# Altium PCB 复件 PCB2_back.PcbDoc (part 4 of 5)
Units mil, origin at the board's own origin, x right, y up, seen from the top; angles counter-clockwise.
Board outline 6299 x 3937 mil, 4 copper layers (TopLayer, GROUND, VCC, BottomLayer); 290 components, 470 nets, 2252 pads, 827 vias.
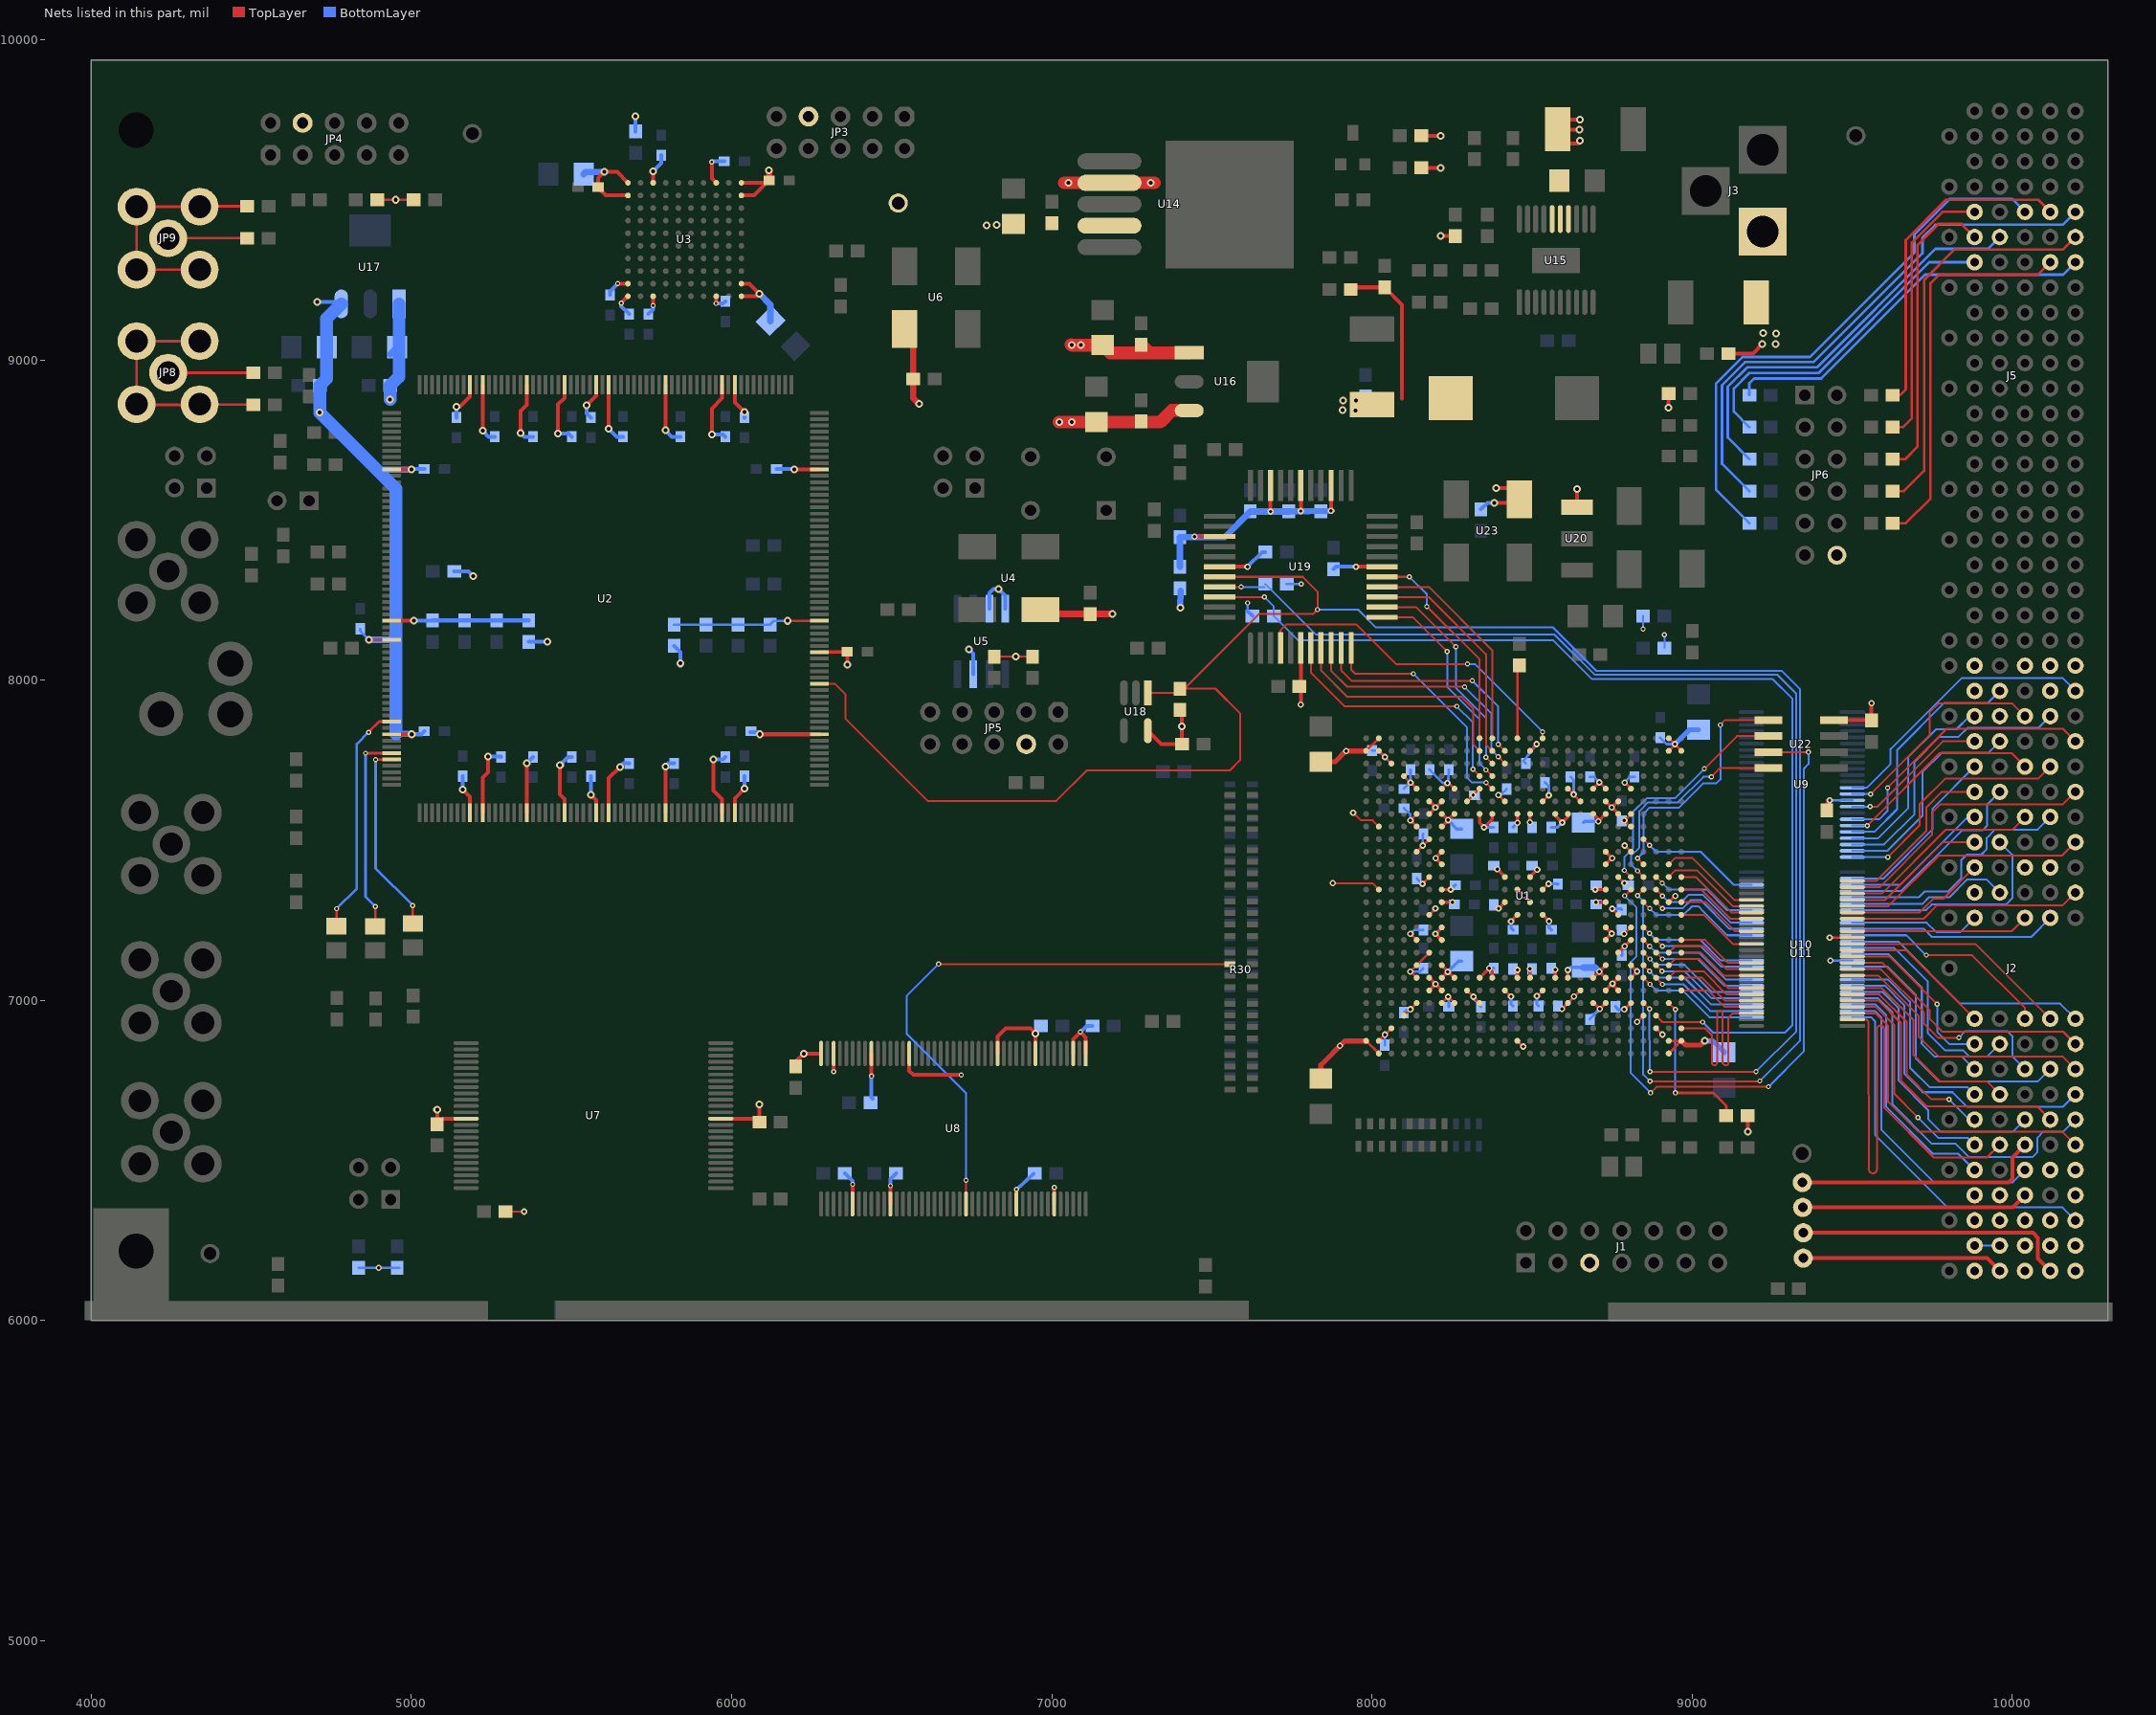
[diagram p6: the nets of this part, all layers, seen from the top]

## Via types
v1: diameter 16, hole 8, TopLayer to BottomLayer, 408 vias
v2: diameter 20, hole 10, TopLayer to BottomLayer, 220 vias
v3: diameter 24, hole 12, TopLayer to BottomLayer, 196 vias
v4: diameter 56.69, hole 56.69, TopLayer to BottomLayer, 2 vias
v5: diameter 20, hole 0, TopLayer to BottomLayer, 1 vias

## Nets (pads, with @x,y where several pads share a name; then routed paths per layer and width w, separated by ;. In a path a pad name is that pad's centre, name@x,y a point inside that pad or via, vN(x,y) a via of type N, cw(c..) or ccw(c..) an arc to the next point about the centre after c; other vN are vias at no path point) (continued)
P_AD22: U1.L4 U10.34 | length 379.9
  TopLayer w6: U1.L4@8847.89,7227.7 v1(8866.59,7209)
  BottomLayer w6: v1(8866.59,7209) 8886.59,7189 9025,7189 9089.59,7124.41 U10.34@9185.04,7124.41
P_AD23: U1.K1 U11.38 | length 248.6
  TopLayer w6: U1.K1@8966,7188.33 9040.67,7188.33 9112.15,7116.85 U11.38@9185.04,7116.85
P_AD24: U1.K4 U10.31 | length 388.1
  TopLayer w6: U1.K4@8847.89,7188.33 v1(8867.22,7169)
  BottomLayer w6: v1(8867.22,7169) 8887.22,7149 9021,7149 9104.65,7065.35 U10.31@9185.04,7065.35
P_AD25: U1.J1 U11.40 | length 248.6
  TopLayer w6: U1.J1@8966,7148.96 9026.04,7148.96 9097.52,7077.48 U11.40@9185.04,7077.48
P_AD26: U1.J3 U10.30 | length 340.6
  TopLayer w6: U1.J3@8887.26,7148.96 v1(8907.22,7129)
  BottomLayer w6: v1(8907.22,7129) 9017,7129 9100.33,7045.67 U10.30@9185.04,7045.67
P_AD27: U1.H2 U11.42 | length 304.1
  TopLayer w6: U1.H2@8926.63,7109.59 8946.04,7129 9023,7129 9113.89,7038.11 U11.42@9185.04,7038.11
P_AD28: U1.J4 U10.29 | length 388.1
  TopLayer w6: U1.J4@8847.89,7148.96 v1(8867.85,7129)
  BottomLayer w6: v1(8867.85,7129) 8885.85,7111 8976,7111 9061.01,7025.98 U10.29@9185.04,7025.98
P_AD29: U1.G2 U11.43 | length 297.1
  TopLayer w6: U1.G2@8926.63,7070.22 8947.41,7091 9035,7091 9107.58,7018.43 U11.43@9185.04,7018.43
P_AD30: U1.H3 U10.28 | length 340.6
  TopLayer w6: U1.H3@8887.26,7109.59 v1(8905.85,7091)
  BottomLayer w6: v1(8905.85,7091) 8976,7091 9060.7,7006.3 U10.28@9185.04,7006.3
P_AD31: U1.G1 U11.44 | length 248.6
  TopLayer w6: U1.G1@8966,7070.22 9030.78,7070.22 9102.26,6998.74 U11.44@9185.04,6998.74
P_CBE0: U1.V4 U10.46 | length 396.2
  TopLayer w6: U1.V4@8847.89,7503.29 v1(8867.18,7484)
  BottomLayer w6: v1(8867.18,7484) 8887.18,7464 9027,7464 9130.37,7360.63 U10.46@9185.04,7360.63
P_CBE1: U1.T2 U11.28 | length 320.4
  TopLayer w6: U1.T2@8926.63,7424.55 8946.08,7444 9001,7444 9131.3,7313.7 U11.28@9185.04,7313.7
P_CBE2: U1.M1 U11.35 | length 256.8
  TopLayer w6: U1.M1@8966,7267.07 9035.93,7267.07 9127.09,7175.9 U11.35@9185.04,7175.9
P_CBE3: U1.J2 U11.39 | length 296.5
  TopLayer w6: U1.J2@8926.63,7148.96 8946.67,7169 9035,7169 9106.83,7097.16 U11.39@9185.04,7097.16
P_CLK: U1.C1 U11.46 | length 796.4
  TopLayer w6: U1.C1@8966,6912.74 9039.26,6912.74 9062,6890 9062,6802 9066,6798 9073,6798 9078,6803 9078,6961 9084,6967 9090,6967 9095,6962 9095,6803 9101,6797 9109,6797 9113,6801 9113,6946 9126.37,6959.37 U11.46@9185.04,6959.37
P_DEVSEL: U1.P1 U11.31 | length 256.8
  TopLayer w6: U1.P1@8966,7345.81 9028.19,7345.81 9119.35,7254.65 U11.31@9185.04,7254.65
P_EN: R61.1 U1.E2 | length 495.7
  TopLayer w6: U1.E2@8926.63,6991.48 v1(8947,6971.11)
  TopLayer w8: v1(8947,6711) 9066,6711 9106.54,6670.46 R61.1@9106.54,6640
  BottomLayer w6: v1(8947,6711) v1(8947,6971.11)
P_FRAME: U1.N4 U10.38 | length 401.8
  TopLayer w6: U1.N4@8847.89,7306.44 v1(8867.33,7287)
  BottomLayer w6: v1(8867.33,7287) 8887.33,7267 8973,7267 8999,7293 9020,7293 9036,7277 ; 9035.5,7276.5 9108.85,7203.15 U10.38@9185.04,7203.15
P_GNT: U1.H4 U10.27 | length 388.1
  TopLayer w6: U1.H4@8847.89,7109.59 v1(8866.48,7091)
  BottomLayer w6: v1(8866.48,7091) 8886.48,7071 8975,7071 9059.39,6986.61 U10.27@9185.04,6986.61
P_IDSEL: U1.K3 U10.33 | length 332.4
  TopLayer w6: U1.K3@8887.26,7188.33 v1(8906.59,7169)
  BottomLayer w6: v1(8906.59,7169) 9026,7169 9090.27,7104.73 U10.33@9185.04,7104.73
P_INTA: U1.G4 U10.25 | length 388.1
  TopLayer w6: U1.G4@8847.89,7070.22 v1(8868.11,7050)
  BottomLayer w6: v1(8868.11,7050) 8887.11,7031 8970,7031 9053.75,6947.24 U10.25@9185.04,6947.24
P_IRDY: U1.N1 U11.33 | length 256.8
  TopLayer w6: U1.N1@8966,7306.44 9042.56,7306.44 9133.73,7215.27 U11.33@9185.04,7215.27
P_PAR: U1.P3 U10.40 | length 358.8
  TopLayer w6: U1.P3@8887.26,7345.81 v1(8907.07,7326)
  BottomLayer w6: v1(8907.07,7326) 8926.07,7307 8966,7307 8988,7329 9034,7329 9120.48,7242.52 U10.40@9185.04,7242.52
P_PERR: U1.R1 U11.30 | length 265
  TopLayer w6: U1.R1@8966,7385.18 9010.82,7385.18 9121.67,7274.33 U11.30@9185.04,7274.33
P_REQ: U1.F1 U11.45 | length 240.5
  TopLayer w6: U1.F1@8966,7030.85 9049.15,7030.85 9100.94,6979.06 U11.45@9185.04,6979.06
P_RST: U1.G3 U10.26 | length 340.6
  TopLayer w6: U1.G3@8887.26,7070.22 v1(8907.48,7050)
  BottomLayer w6: v1(8907.48,7050) 8973,7050 9056.07,6966.93 U10.26@9185.04,6966.93
P_SERR: U1.R2 U11.29 | length 312.6
  TopLayer w6: U1.R2@8926.63,7385.18 8946.45,7405 9016,7405 9126.99,7294.02 U11.29@9185.04,7294.02
P_STOP: U1.R3 U10.42 | length 340.6
  TopLayer w6: U1.R3@8887.26,7385.18 v1(8906.44,7366)
  BottomLayer w6: v1(8906.44,7366) 8926.44,7346 9044,7346 9108.11,7281.89 U10.42@9185.04,7281.89
P_TRDY: U1.N3 U10.39 | length 353.9
  TopLayer w6: U1.N3@8887.26,7306.44 v1(8906.7,7287)
  BottomLayer w6: v1(8906.7,7287) 8970,7287 8996,7313 9026,7313 9116.17,7222.84 U10.39@9185.04,7222.84
PCI_EEAI: R78.1 U1.L5 | length 29.2
  TopLayer w8: v2(8787,7208) U1.L5@8808.52,7227.7
PXI_3.3V: J2.C6 pad.1@9344,6431 | length 783.2
  TopLayer w12: pad.1@9344,6431 9988,6431 10000,6443 10000,6509.51 J2.C6@10039.37,6548.88
PXI_+12V: J2.D1 pad.4 | length 630.1
  TopLayer w12: pad.4@9347,6195 9920.81,6195 J2.D1@9960.63,6155.18
PXI_-12V: J2.B1 pad.3 | length 858.2
  TopLayer w12: pad.3@9347,6274 10064,6274 10080,6258 10080,6193.29 J2.B1@10118.11,6155.18
PXI_ACK64#: J2.E24
PXI_AD0: J2.D24 U9.20 | length 758.2
  BottomLayer w6: U9.20@9500,7525.98 9569,7525.98 9640,7596.98 9640,7782 9786,7928 9922.49,7928 J2.D24@9965.49,7971
PXI_AD1: J2.A24 U9.13 | length 882.9
  BottomLayer w6: U9.13@9500,7663.78 9544.78,7663.78 9619.67,7738.67 9619.67,7784.67 9842,8007 10155.99,8007 J2.A24@10196.85,7966.14
PXI_AD2: J2.E23 U9.21 | length 633.3
  BottomLayer w6: U9.21@9500,7506.3 9581,7506.3 9674,7599.3 9674,7759 9761.41,7846.41 9825.41,7846.41 9866.4,7887.4 J2.E23@9881.89,7887.4
PXI_AD3: J2.C23 U9.14 | length 714.5
  TopLayer w6: v1(9557.09,7644.1) 9741,7828 9741,7899 9769,7927 9999.77,7927 J2.C23@10039.37,7887.4
  BottomLayer w6: U9.14@9500,7644.1 v1(9557.09,7644.1)
PXI_AD4: J2.B23 U9.22 | length 879.2
  BottomLayer w6: U9.22@9500,7486.61 9599,7486.61 9694,7581.61 9694,7744 9772.9,7822.9 9831.9,7822.9 9860,7851 10081.71,7851 J2.B23@10118.11,7887.4
PXI_AD5: J2.E22 U9.16 | length 466.4
  TopLayer w6: v1(9555.73,7604.73) 9578.73,7604.73 9782.66,7808.66 J2.E22@9881.89,7808.72
  BottomLayer w6: U9.16@9500,7604.73 v1(9555.73,7604.73)
PXI_AD6: J2.D22 U9.23 | length 682.5
  BottomLayer w6: U9.23@9500,7466.93 9610,7466.93 9719,7575.93 9719,7713 9779,7773 9924.97,7773 J2.D22@9960.63,7808.72
PXI_AD7: J2.A22 U9.18 | length 872.4
  TopLayer w6: v1(9610,7663) 9795,7848 10157.51,7848 J2.A22@10196.85,7808.72
  BottomLayer w6: U9.18@9500,7565.35 9584.35,7565.35 9610,7591 v1(9610,7663)
PXI_AD8: J2.C21 U9.19 | length 650.5
  TopLayer w6: v1(9546.67,7545.67) 9773,7772 9997.29,7772 J2.C21@10039.37,7729.92
  BottomLayer w6: U9.19@9500,7545.67 v1(9546.67,7545.67)
PXI_AD9: J2.B21 U9.24 | length 773.9
  TopLayer w6: v1(9611.25,7447.24) 9710.28,7546.28 9710.28,7612.28 9790,7692 10080.19,7692 J2.B21@10118.11,7729.92
  BottomLayer w6: U9.24@9500,7447.24 v1(9611.25,7447.24)
PXI_AD10: J2.E20 U11.24 | length 540
  TopLayer w6: U11.24@9500,7372.76 9574.75,7372.76 9731.25,7529.25 9731.25,7602.25 9780.18,7651.18 J2.E20@9881.89,7651.24
PXI_AD11: J2.D20 U10.4 | length 628.1
  BottomLayer w6: U10.4@9500,7340.94 9651.94,7340.94 9842,7531 9907,7531 9921,7545 9921,7611.55 J2.D20@9960.63,7651.24
PXI_AD12: J2.A20 U11.23 | length 860.8
  TopLayer w6: U11.23@9500,7353.07 9585.07,7353.07 9748.62,7516.62 9748.62,7585.62 9775,7612 10157.67,7612 J2.A20@10196.85,7651.24
PXI_AD13: J2.E19 U10.3 | length 469.6
  BottomLayer w6: U10.3@9500,7360.63 9648.63,7360.63 9860.44,7572.44 J2.E19@9881.89,7572.44
PXI_AD14: J2.C19 U11.22 | length 638.4
  TopLayer w6: U11.22@9500,7333.39 9592.39,7333.39 9791,7532 9998.93,7532 J2.C19@10039.37,7572.44
PXI_AD15: J2.B19 U10.5 | length 775.5
  BottomLayer w6: U10.5@9500,7321.26 9707.37,7321.26 9726,7339.89 9798.89,7339.89 9840,7381 9840,7437 9858,7455 9903,7455 9920,7472 9920,7507 9946,7533 10078.67,7533 J2.B19@10118.11,7572.44
PXI_AD16: J2.C11 U10.11 | length 666.7
  TopLayer w6: v1(9731,7141) 9874,7141 10039.37,6975.63 J2.C11@10039.37,6942.52
  BottomLayer w6: U10.11@9500,7203.15 9668.85,7203.15 v1(9731,7141)
PXI_AD17: J2.B11 U11.14 | length 714.8
  TopLayer w6: U11.14@9500,7175.9 9884.72,7175.9 J2.B11@10118.11,6942.52
PXI_AD18: J2.A11 U10.12 | length 796.7
  BottomLayer w6: U10.12@9500,7183.47 9643.53,7183.47 9837,6990 10149.37,6990 J2.A11@10196.85,6942.52
PXI_AD19: J2.E10 U11.12 | length 545.8
  TopLayer w6: U11.12@9500,7136.53 9616.47,7136.53 v1(9765,6988)
  BottomLayer w6: v1(9765,6988) 9765,6901 9802.22,6863.78 J2.E10@9881.89,6863.84
PXI_AD20: J2.D10 U10.13 | length 711.9
  BottomLayer w6: U10.13@9500,7163.78 9630.22,7163.78 9736,7058 9736,6897.39 9789,6844.39 9845.61,6844.39 9866,6824 9920.85,6824 J2.D10@9960.63,6863.84
PXI_AD21: J2.A10 U11.11 | length 818.1
  TopLayer w6: U11.11@9500,7116.85 9594.15,7116.85 9742,6969 9742,6941 9781,6902 10158.63,6902 J2.A10@10196.85,6863.84
PXI_AD22: J2.E9 U10.14 | length 633.7
  BottomLayer w6: U10.14@9500,7144.1 9612.91,7144.1 9717,7040 9717,6864 9757,6824 9842.93,6824 J2.E9@9881.89,6785.04
PXI_AD23: J2.C9 U11.10 | length 743.3
  TopLayer w6: U11.10@9500,7097.16 9588.83,7097.16 9724,6962 9724,6927 9768,6883 v1(9833,6883)
  BottomLayer w6: v1(9833,6883) 9852,6903 9985,6903 10000,6888 10000,6824.47 J2.C9@10039.37,6785.1
PXI_AD24: J2.E8 U10.18 | length 651.3
  BottomLayer w6: U10.18@9500,7065.35 9610.65,7065.35 9680,6996 9680,6790 9742,6728 9860.19,6728 J2.E8@9881.89,6706.3
PXI_AD25: J2.D8 U11.7 | length 661.9
  TopLayer w6: U11.7@9500,7038.11 9590.89,7038.11 9691.07,6937.93 9691.07,6828.93 9773,6747 9919.93,6747 J2.D8@9960.63,6706.3
PXI_AD26: J2.A8 U10.19 | length 994.5
  BottomLayer w6: U10.19@9500,7045.67 9601.33,7045.67 9663,6984 9663,6770 9720,6713 9813,6713 9858,6668 10158.55,6668 J2.A8@10196.85,6706.3
PXI_AD27: J2.E7 U11.6 | length 642.4
  TopLayer w6: U11.6@9500,7018.43 9584.58,7018.43 9670,6933 9670,6768 9747,6691 v1(9802,6691)
  BottomLayer w6: v1@9802,6689 v1@9804,6689 ; v1(9802,6691) 9865.44,6627.56 J2.E7@9881.89,6627.62
PXI_AD28: J2.C7 U10.20 | length 885.1
  BottomLayer w6: U10.20@9500,7025.98 9594.01,7025.98 9645,6975 9645,6749 9737,6657 9737,6629 9777,6589 10000.81,6589 J2.C7@10039.37,6627.62
PXI_AD29: J2.B7 U11.5 | length 877.3
  TopLayer w6: U11.5@9500,6998.74 9582.26,6998.74 9652,6929 9652,6749 9732,6669 10076.67,6669 J2.B7@10118.11,6627.62
PXI_AD30: J2.A7 U10.21 | length 1145.6
  BottomLayer w6: U10.21@9500,7006.3 9580.7,7006.3 9625,6962 9625,6675 9747,6553 9822,6553 9865,6510 10062,6510 10078,6526 10078,6571 10097,6590 10159.29,6590 J2.A7@10196.85,6627.62
PXI_AD31: J2.E6 U11.4 | length 685.5
  TopLayer w6: U11.4@9500,6979.06 9573.94,6979.06 9631,6922 9631,6708 v1(9705,6634)
  BottomLayer w6: v1(9705,6634) 9768,6571 9859.71,6571 J2.E6@9881.89,6548.82
PXI_BRSVP1A5: J2.A5
PXI_BRSVP1B5: J2.B5
PXI_C/BE0#: J2.E21 U10.2 | length 569
  BottomLayer w6: U10.2@9500,7380.31 9597,7380.31 9751,7534.31 9751,7599.03 J2.E21@9884.97,7733
PXI_C/BE1#: J2.E18 U11.21 | length 467.3
  TopLayer w6: U11.21@9500,7313.7 9602.7,7313.7 9782.7,7493.7 J2.E18@9892.7,7493.7
PXI_C/BE2#: J2.E11 U11.13 | length 470.4
  TopLayer w6: U11.13@9500,7156.22 9668.19,7156.22 J2.E11@9881.89,6942.52
PXI_C/BE3#: J2.A9 U11.9 | length 856.1
  TopLayer w6: U11.9@9500,7077.48 9581.52,7077.48 9708,6951 9708,6886 9769,6825 10156.89,6825 J2.A9@10196.85,6785.04
PXI_CLK10: J5.E17 R89.1 | length 947.1
  TopLayer w8: R89.1@9625.46,8690 9665,8690 9704,8729 9704,9359 9770,9425 9840.42,9425 J5.E17@9881.89,9383.53
PXI_DEVSEL#: J2.A16 U11.18 | length 730.6
  TopLayer w6: U11.18@9500,7254.65 9722.65,7254.65 9765,7297 10157.63,7297 J2.A16@10196.85,7336.22
PXI_ENUM#: J2.C25
PXI_FRAME#: J2.B15 U10.10 | length 658
  BottomLayer w6: U10.10@9500,7222.84 9724.17,7222.84 9749,7198 10058.63,7198 J2.B15@10121.63,7261
PXI_GNT#: J2.E5 U10.22 | length 764
  BottomLayer w6: U10.22@9500,6986.61 9573.39,6986.61 9606,6954 9606,6667 9752,6521 9830.97,6521 J2.E5@9881.89,6470.14
PXI_IDSEL: J2.B9 U10.16 | length 898.9
  BottomLayer w6: U10.16@9500,7104.73 9610.27,7104.73 9699,7016 9699,6818 9771,6746 10079.07,6746 J2.B9@10118.11,6785.04
PXI_INTA#: J2.A3 U10.24 | length 1173.8
  BottomLayer w6: U10.24@9500,6947.24 9558.75,6947.24 9571,6935 9571,6580 9798,6353 10156.51,6353 J2.A3@10196.85,6312.66 ; J2.A3@10196.88,6312.63 J2.A3@10201.25,6317
PXI_INTB#: J2.B3
PXI_INTC#: J2.C3
PXI_INTD#: J2.E3
PXI_INTP: J2.D4
PXI_INTS: J2.E4
PXI_IPMB_PWR: J2.A4
PXI_IPMB_SCL: J2.B17
PXI_IPMB_SDA: J2.C17
PXI_IRDY#: J2.C15 U11.16 | length 556.9
  TopLayer w6: U11.16@9500,7215.27 9997.16,7215.27 J2.C15@10039.37,7257.54
PXI_LOCK#: J2.E16
PXI_PAR: J2.D18 U10.7 | length 706.4
  BottomLayer w6: U10.7@9500,7281.89 9730.89,7281.89 9748,7299 9980,7299 10000,7319 10000,7454.33 J2.D18@9960.63,7493.7
PXI_PCLK: J2.D6 U11.2 | length 1714.1
  TopLayer w6: U11.2@9500,6939.69 9544.32,6939.69 9551,6933 9551.15,6474.98 ccw(c9564,6473) 9577,6473 9577,6911 cw(c9588,6910) 9599.05,6910 ; 9599,6910 9599,6665 9755,6509 9920.81,6509 J2.D6@9960.63,6548.82
PXI_PERR#: J2.E17 U11.19 | length 440.1
  TopLayer w6: U11.19@9500,7274.33 9710.33,7274.33 9754,7318 9784.93,7318 J2.E17@9881.89,7415.02
PXI_REQ64#: J2.B25
PXI_REQ#: J2.A6 U11.3 | length 1005.7
  TopLayer w6: U11.3@9500,6959.37 9572.63,6959.37 9612,6920 9612,6683 9706,6589 10156.67,6589 J2.A6@10196.85,6548.82
PXI_RST#: J2.C5 U10.23 | length 982.3
  BottomLayer w6: U10.23@9500,6966.93 9570.07,6966.93 9590,6947 9590,6596 9754,6432 10001.29,6432 J2.C5@10039.37,6470.14
PXI_SERR#: J2.A18 U11.20 | length 779.6
  TopLayer w6: U11.20@9500,7294.02 9613.01,7294.02 9771,7452 10155.15,7452 J2.A18@10196.85,7493.7
PXI_START: J5.D17 R53.2 | length 1297.3
  BottomLayer w8: R53.2@9178.54,8690 9111,8757.54 9111,8916 9172,8977 9390,8977 9760,9347 9924.1,9347 J5.D17@9960.63,9383.53
PXI_STOP#: J2.D16 U10.6 | length 508.8
  BottomLayer w6: U10.6@9500,7301.57 9719.58,7301.57 9740.03,7322.03 9803.03,7322.03 9858,7377 9919.85,7377 J2.D16@9960.63,7336.22
PXI_TCK: J2.A2
PXI_TDIO: J2.D2 J2.E2 | length 78.7
  BottomLayer w6: J2.E2@9881.89,6233.92 J2.D2@9960.63,6233.92
PXI_TMS: J2.C2
PXI_TRDY#: J2.E15 U10.9 | length 428.8
  BottomLayer w6: U10.9@9500,7242.52 9732.48,7242.52 9762,7213 9837.41,7213 J2.E15@9893.41,7269
PXI_TRIG0: J5.B16 R91.1 | length 1223.8
  TopLayer w8: R91.1@9625.46,8490 9667,8490 9744,8567 9744,9239 9770,9265 10078.32,9265 J5.B16@10118.11,9304.79
PXI_TRIG1: J5.A16 R20.2 | length 1212.1
  BottomLayer w8: R20.2@9178.54,8890 9178.54,8927.54 9193,8942 9403,8942 9727,9266 10158.06,9266 J5.A16@10196.85,9304.79
PXI_TRIG2: J5.A17 R90.1 | length 1249.2
  TopLayer w8: R90.1@9625.46,8590 9661,8590 9724,8653 9724,9249 9820,9345 10158.32,9345 J5.A17@10196.85,9383.53
PXI_TRIG3: J5.A18 R60.2 | length 1723.2
  BottomLayer w8: R60.2@9178.54,8590 9093,8675.54 9093,8921 9165,8993 9379,8993 9719,9333 9719,9382 9759,9422 10156.58,9422 J5.A18@10196.85,9462.27
PXI_TRIG4: J5.B18 R75.1 | length 1033.9
  TopLayer w8: R75.1@9625.46,8890 9649,8890 9667,8908 9667,9374 9793,9500 10080.38,9500 J5.B18@10118.11,9462.27
PXI_TRIG5: J5.C18 R63.2 | length 1733.1
  BottomLayer w8: R63.2@9178.54,8490 9074,8594.54 9074,8926 9157,9009 9368,9009 9694,9335 9694,9392 9804,9502 9999.64,9502 J5.C18@10039.37,9462.27
PXI_TRIG6: J5.E18 R85.1 | length 855.9
  TopLayer w8: R85.1@9625.46,8790 9658,8790 9686,8818 9686,9366 9782.27,9462.27 J5.E18@9881.89,9462.27
PXI_TRIG7: J5.E16 R21.2 | length 1056.1
  BottomLayer w8: R21.2@9178.54,8790 9130,8838.54 9130,8911 9178,8959 9395,8959 9740.79,9304.79 J5.E16@9881.89,9304.79
PXI_TRST#: J2.C1
PXI_VIO: J2.C4 pad.2@9345,6353 | length 710.3
  TopLayer w12: pad.2@9345,6353 10000.97,6353 J2.C4@10039.37,6391.4
SCL: R87.2 U1.E4 U19.41 | length 3729.7
  TopLayer w6: U19.41@7523.54,8290.94 v1(7591.06,8290.94) ; U1.E4@8847.89,6991.48 v1(8866.37,6973) ; v1(8868,6777) v1(9199,6777)
  BottomLayer w6: v1(7591.06,8290.94) R87.2@7665.06,8290.94 ; R87.2@7666.54,8300 7824.54,8142 8570.03,8142 8695.03,8017 9265,8017 9325,7957 9325,6903 v1(9199,6777) ; v1@8866.37,6778.63 v1(8868,6777) v1(8866.37,6973)
SDA: R88.2 U1.D3 U19.42 | length 3414.3
  TopLayer w6: U19.42@7523.54,8259.45 v1(7663.55,8259.45) ; U1.D3@8887.26,6952.11 8907.37,6932 v1(9033,6932)
  BottomLayer w6: v1(7663.55,8259.45) 7693.46,8229.54 R88.2@7693.46,8200 7768.46,8125 8565,8125 8686,8004 9250,8004 9313,7941 9313,6923 9289,6899 9066,6899 v1(9033,6932)
SDCKE: R30.6 U8.67 | length 1777.3
  TopLayer w6: v1(6646,7113) R30.6@7555.84,7113 ; U8.67@6731.98,6364 v1(6731.98,6437.98)
  BottomLayer w6: v1(6646,7113) 6546,7013 6546,6896 6731.98,6710.02 v1(6731.98,6437.98)
SERIN+: C2.2 JP8.1 | length 266.5
  TopLayer w8: JP8.1@4240,8960 C2.2@4506.54,8960
SERIN-: C1.2 JP8.2 | length 759.3
  TopLayer w6: JP8.2@4338.43,8861.58 JP8.2@4340,8860
  TopLayer w8: JP8.2@4336.43,8859.58 4141.57,8859.58 JP8.2@4141.57,9058.42 JP8.2@4338.43,9058.42 ; JP8.2@4340,8860 C1.2@4506.54,8860
SEROUT+: C3.2 JP9.1 | length 246.5
  TopLayer w8: JP9.1@4240,9380 C3.2@4486.54,9380
SEROUT-: C4.2 JP9.2 | length 739.3
  TopLayer w8: JP9.2@4338.43,9281.58 JP9.2@4141.57,9281.58 JP9.2@4141.57,9478.42 JP9.2@4338.43,9478.42 4340,9480 C4.2@4486.54,9480
SYSTEM_RESET#: R71.1 U1.P4 U2.17 U18.1 U19.40 | length 6785.2
  TopLayer w6: U2.17@6274.31,7988.25 6322.75,7988.25 6356,7955 6356,7879 6612,7623 7014,7623 7109,7718 7556,7718 7588,7750 7588,7896 7510.54,7973.46 R71.1@7400,7973.46 7386.54,7960 U18.1@7300,7960 ; R71.1@7414.46,7973.46 7648,8207 7817,8207 v1(7830,8220) 7830,8276 7783.56,8322.44 U19.40@7523.54,8322.44 ; v1(8829,7326.92) U1.P4@8847.89,7345.81 ; v1(8868,6747) 9211,6747 v1(9211,6748)
  BottomLayer w6: v1(7830,8220) 7956,8220 8011,8165 8564,8165 8700,8029 9279,8029 9337,7971 9337,6874 v1(9211,6748) ; v1(8829,7326.92) 8847,7308.92 8847,6768 v1(8868,6747)
USER_LED0: DS1.1 U2.176 | length 610.3
  TopLayer w8: v1(4888.03,7752.03) U2.176@4937.69,7752.03 ; DS1.1@5004,7239.4 v1(5004,7296)
  BottomLayer w8: v1(4888.03,7752.03) 4888.03,7411.97 v1(5004,7296)
USER_LED1: DS2.1 U2.175 | length 634.8
  TopLayer w8: v1(4856.72,7771.72) U2.175@4937.69,7771.72 ; DS2.1@4887,7230.4 v1(4887,7293)
  BottomLayer w8: v1(4856.72,7771.72) 4856.72,7323.28 v1(4887,7293)
USER_LED2: DS3.1 U2.170 | length 732.4
  TopLayer w8: DS3.1@4766,7231.4 v1(4766,7286) ; v1(4866,7837) 4899.14,7870.14 U2.170@4937.69,7870.14
  BottomLayer w8: v1(4766,7286) 4829,7349 4829,7800 v1(4866,7837)
V1.4: C42.1 C43.1 C44.1 C50.1 C51.1 C52.1 C53.1 C60.1 C63.2 C70.1 C71.1 C72.1 C78.2 C79.1 C80.1 C81.1 C87.1 C90.2 C126.2 C138.1 C145.1 C148.1 C149.1 C151.1 L1.2 R69.2 R70.2 U1.AA6 U1.AA7 U1.AA20 U1.AA21 U1.F6 U1.F7 U1.F20 U1.F21 U1.G6 U1.G7 U1.G8 U1.G10 U1.G11 U1.G13 U1.G14 U1.G16 U1.G17 U1.G19 U1.G20 U1.G21 U1.H7 U1.H20 U1.K7 U1.K20 U1.L7 U1.L20 U1.M12 U1.M14 U1.N7 U1.N13 U1.N15 U1.N20 U1.P7 U1.P12 U1.P14 U1.P20 U1.R13 U1.R15 U1.T7 U1.T20 U1.U7 U1.U20 U1.W20 U1.Y6 U1.Y7 U1.Y8 U1.Y10 U1.Y11 U1.Y13 U1.Y14 U1.Y16 U1.Y17 U1.Y19 U1.Y20 U1.Y21 | length 2649.8
  TopLayer w8: v2@8473,7327 v2@8474,7326 ; U1.P12@8532.93,7345.81 v2(8551.12,7364)
  TopLayer w10: U1.F21@8178.6,7030.85 v2(8198.23,7050.48) ; U1.G21@8178.6,7070.22 U1.F20@8217.97,7030.85 ; U1.Y21@8178.6,7582.03 v2@8198.39,7601.83 ; U1.AA21@8178.6,7621.4 v2(8198.17,7601.83) v2@8198.39,7601.83 ; U1.G20@8217.97,7070.22 v2(8236.57,7088.82) ; U1.H20@8217.97,7109.59 U1.G19@8257.34,7070.22 ; U1.K20@8217.97,7188.33 8217.4,7188.33 v2(8198,7207.73) U1.L20@8217.97,7227.7 ; U1.N20@8217.97,7306.44 v2(8250.57,7306.44) ; U1.P20@8217.97,7345.81 v2(8245.81,7345.81) ; U1.T20@8217.97,7424.55 v2(8199,7443.52) 8199,7444.95 U1.U20@8217.97,7463.92 ; U1.W20@8217.97,7542.66 8237.65,7562.35 v2@8238.12,7562.81 ; U1.Y20@8217.97,7582.03 v2(8237.19,7562.81) v2@8238.12,7562.81 ; U1.AA20@8217.97,7621.4 v2@8198.39,7601.83 ; U1.Y19@8257.34,7582.03 v2@8238.12,7562.81 ; U1.G17@8336.08,7070.22 v2(8365.86,7100) 8375.45,7090.41 U1.G16@8375.45,7070.22 ; U1.Y17@8336.08,7582.03 8336.08,7553.92 v2(8350,7540) 8375.45,7565.45 U1.Y16@8375.45,7582.03 ; v2(8391,7409) U1.R15@8414.82,7385.18 ; v2(8395.38,7287) U1.N15@8414.82,7306.44 ; v2(8434,7246.88) U1.M14@8454.19,7267.07 ; v2(8454,7095) 8454.19,7094.81 U1.G14@8454.19,7070.22 ; U1.P14@8454.19,7345.81 8473,7327 v2(8475,7327) 8493.56,7308.44 U1.N13@8493.56,7306.44 ; v2(8454.19,7554.19) U1.Y14@8454.19,7582.03 ; U1.G13@8493.56,7070.22 v2(8493.56,7098.56) ; U1.R13@8493.56,7385.18 v2(8516,7407.62) ; v2(8493.56,7555.56) U1.Y13@8493.56,7582.03 ; U1.M12@8532.93,7267.07 v2(8553,7247) ; U1.G11@8572.3,7070.22 v2(8572.3,7095.7) ; U1.Y11@8572.3,7582.03 8572.3,7576.7 v2(8594,7555) 8611.67,7572.67 U1.Y10@8611.67,7582.03 ; U1.G10@8611.67,7070.22 v2(8611.67,7094.67) ; U1.G8@8690.41,7070.22 8690.41,7070.41 8729.59,7109.59 U1.H7@8729.78,7109.59 ; U1.Y8@8690.41,7582.03 8706.75,7565.69 v2(8706.75,7559) U1.Y7@8729.78,7582.03 ; v2(8697.19,7345.81) U1.P7@8729.78,7345.81 ; v2(8699.56,7306.44) U1.N7@8729.78,7306.44 ; v2(8710,7090) U1.G7@8729.78,7070.22 ; U1.F7@8729.78,7030.85 U1.G6@8769.15,7070.22 ; U1.K7@8729.78,7188.33 8729.78,7189.26 v2(8749,7208.48) U1.L7@8729.78,7227.7 ; U1.T7@8729.78,7424.55 8748.93,7443.7 v2(8750,7443.7) U1.U7@8729.78,7463.92 ; U1.AA7@8729.78,7621.4 U1.Y6@8769.15,7582.03 ; v2(8748.94,7602.24) 8768.09,7621.4 U1.AA6@8769.15,7621.4 ; v2(8750.67,7051.74) 8750.67,7049.33 U1.F6@8769.15,7030.85 U1.F6@8769.15,7032.32
  TopLayer w12: R69.2@7933.46,9220 7940,9226.54 R70.2@8040,9226.54 8094,9172.54 8094,8879
  BottomLayer w10: v2(8236.57,7088.82) 8270.31,7122.57 C149.1@8280,7122.57 ; v2(8237.19,7562.81) 8264.88,7535.12 C148.1@8280,7535.12 ; v2(8245.81,7345.81) C71.1@8260,7360 ; v2(8350,7540) C53.1@8380,7540 ; v2(8365.86,7100) C79.1@8380,7100 ; v2(8434,7246.88) 8434,7226.99 C78.2@8440.99,7220 ; C42.1@8440,7540 v2(8454.19,7554.19) ; v2(8551.12,7364) 8578.99,7364 C90.2@8580,7362.99 ; v2(8553,7247) 8553,7227 C70.1@8560,7220 ; C51.1@8560,7540 8579,7540 v2(8594,7555) ; v2(8611.67,7094.67) 8619.57,7102.57 C151.1@8660,7102.57 ; C145.1@8660,7555.12 8663.88,7559 v2(8706.75,7559)
  BottomLayer w12: v3(7949,8842) 7980,8873 C126.2@7980,8886.54
  BottomLayer w20: C151.1@8660,7102.57 8697.43,7102.57 v2(8710,7090)
  other v3: 7908,8843 7909,8873 7950,8873
V1.5: C100.1 C101.1 C106.1 C107.1 C111.1 C112.1 C116.1 C117.1 C120.1 C121.1 C123.1 C124.1 C125.2 C137.1 FB1.1 FB2.1 U2.72 U2.81 U2.90 U2.97 U2.103 U2.110 U2.191 U2.198 U2.204 U2.211 U2.220 U2.229 U16.3 | length 2942.8
  TopLayer w8: 5220,8857 5222.14,8859.14 ; U2.97@5478.05,8922.31 U2.97@5480,8920.35
  TopLayer w12: U2.191@5222.14,7585.69 5222.14,7695.14 5239,7712 v3(5239,7761) ; v3(5222.14,8778.86) U2.110@5222.14,8922.31 ; v3(5341,8771) 5341,8840.13 5359.94,8859.06 U2.103@5359.94,8922.31 ; U2.198@5359.94,7585.69 v3(5359.94,7739.94) ; v3(5458,8770) 5458,8861 5478.05,8881.05 U2.97@5478.05,8922.31 ; v3(5464,7735) 5464,7643 5478.05,7628.95 U2.204@5478.05,7585.69 ; U2.211@5615.84,7585.69 5615.84,7693.84 v3(5651,7729) ; v3(5615.84,8785.16) U2.90@5615.84,8922.31 ; U2.220@5793.01,7585.69 v3(5793.01,7730.01) ; v3(5793.01,8779.99) U2.81@5793.01,8922.31 ; v3(5938,8767) 5938,8848 5970.17,8880.17 U2.72@5970.17,8922.31 ; v3(5943,7753) 5943,7655 5970.17,7627.83 U2.229@5970.17,7585.69
  TopLayer w40: v3(7022.88,8805.88) 7338.88,8805.88 7375,8842 U16.3@7429,8842
  BottomLayer w12: v3(5222.14,8778.86) 5241,8760 C124.1@5260,8760 ; v3(5239,7761) 5279,7761 C100.1@5280,7760 ; v3(5341,8771) 5352,8760 C112.1@5380,8760 ; v3(5359.94,7739.94) C106.1@5380,7760 ; FB2.1@5366,8119.54 v3(5424.54,8119.54) ; v3(5458,8770) 5490,8770 C101.1@5500,8760 ; v3(5464,7735) 5489,7760 C111.1@5500,7760 ; v3(5615.84,8785.16) 5641,8760 C121.1@5660,8760 ; v3(5651,7729) 5662,7740 C116.1@5680,7740 ; v3(5793.01,7730.01) 5803,7740 C123.1@5820,7740 ; v3(5793.01,8779.99) 5813,8760 C117.1@5840,8760 ; FB1.1@5820,8106.54 5840,8086.54 v3(5840,8052) ; v3(5938,8767) 5973,8767 C107.1@5980,8760 ; v3(5943,7753) 5973,7753 C120.1@5980,7760
  other v3: 7062,8805.88
V2.5: C97.1 C103.1 C108.1 C132.2 C143.1 U2.130 U2.157 U2.172 U17.3 | length 2118.1
  TopLayer w8: v3(4866.95,8126.05) U2.157@4937.69,8126.05
  TopLayer w12: U2.172@4937.69,7830.77 v3(5000.77,7830.77) ; U2.130@4937.69,8657.54 v3(5000.54,8657.54)
  BottomLayer w8: C108.1@4840,8160 4840,8153 v3(4866.95,8126.05) ; v3(5000.54,8657.54) v3@5003,8660
  BottomLayer w12: v3(4706,9181) 4781,9181 U17.3@4781,9175 ; v3(5000.77,7830.77) 5030.77,7830.77 C97.1@5040,7840 ; v3@5003,8660 C103.1@5040,8660
  BottomLayer w20: v3(4866.95,8126.05) 4931.05,8126.05 4952,8147 ; 4901.54,8657.54 v3(5000.54,8657.54) ; 4952,7832 4999.54,7832 v3(5000.77,7830.77)
  BottomLayer w40: U17.3@4781,9175 4735.12,9129.12 4735.12,8941.65 C132.2@4713.46,8920 v3(4713.46,8835.54) 4952,8597 4952,7832
V3.3: C5.2 C6.2 C7.2 C8.2 C9.2 C10.2 C11.2 C14.1 C15.1 C16.2 C17.2 C18.2 C19.2 C20.2 C21.2 C22.2 C23.2 C24.2 C25.2 C26.2 C27.1 C37.1 C38.1 C39.1 C40.1 C41.1 C45.1 C46.1 C47.1 C48.1 C49.1 C55.1 C56.1 C57.1 C58.1 C59.1 C65.1 C66.1 C67.1 C68.1 C69.1 C73.1 C74.1 C75.1 C76.1 C77.1 C82.1 C83.1 C84.1 C85.1 C86.1 C95.2 C98.1 C99.1 C104.1 C105.1 C109.1 C110.1 C114.1 C115.1 C119.1 C133.2 C135.1 C144.1 C147.1 C150.1 C152.1 C154.2 C156.2 C158.2 C162.2 C165.2 FB3.1 FB4.2 J1.5 JP3.7 JP4.4 JP5.4 pad.9 R8.2 R14.2 R16.2 R26.2 R27.2 R29.2 R56.1 R57.1 R58.2 R61.2 R71.2 R74.2 R78.2 R80.2 R87.1 R88.1 U1.A2 U1.A25 U1.AA9 U1.AA12 U1.AA15 U1.AA18 U1.AB5 U1.AB7 U1.AB8 U1.AB10 U1.AB17 U1.AB19 U1.AB20 U1.AB22 U1.AC23 U1.AD24 U1.AE1 U1.AE2 U1.AE13 U1.AE25 U1.AE26 U1.AF2 U1.AF25 U1.B1 U1.B2 U1.B14 U1.B25 U1.B26 U1.C3 U1.C24 U1.D4 U1.D23 U1.E5 U1.E7 U1.E8 U1.E10 U1.E17 U1.E19 U1.E20 U1.E22 U1.F9 U1.F12 U1.F15 U1.F18 U1.G5 U1.G22 U1.H5 U1.H22 U1.J6 U1.J21 U1.K5 U1.K22 U1.M6 U1.M21 U1.N2 U1.P25 U1.R6 U1.R21 U1.U5 U1.U22 U1.V21 U1.W5 U1.W22 U1.W25 U1.Y5 U1.Y22 U2.9 U2.22 U2.51 U2.70 U2.92 U2.112 U2.189 U2.209 U2.231 U3.A1 U3.A3 U3.A8 U3.A10 U3.B1 U3.B10 U3.J1 U3.J10 U3.K1 U3.K3 U3.K8 U3.K10 U4.4 U5.3 U5.7 U5.8 U6.4 U7.12 U7.37 U8.1 U8.3 U8.9 U8.15 U8.29 U8.35 U8.41 U8.43 U8.49 U8.55 U8.75 U8.81 U14.4 U18.5 U19.6 U19.17 U19.39 U20.1 U22.8 U23.4 | length 10732.9
  TopLayer w6: 5124.53,6630.53 U7.37@5170.72,6630.53 ; R58.2@5293.46,6340 v2(5352,6340) ; R27.2@6820,8073.46 R26.2@6940,8073.46 ; v2(7877,7366) 8000.93,7366 U1.P25@8021.12,7345.81 ; v2(7941,7586) 7965,7562 8001.78,7562 U1.W25@8021.12,7542.66
  TopLayer w8: R16.2@4893.46,9500 R14.2@5006.54,9500 ; U1.B26@7981.75,6873.37 U1.A25@8021.12,6834 ; U1.AE26@7981.75,7778.88 U1.AF25@8021.12,7818.25 ; U1.B25@8021.12,6873.37 U1.C24@8060.49,6912.74 ; U1.AE25@8021.12,7778.88 U1.AD24@8060.49,7739.51 ; U1.D23@8099.86,6952.11 8119.87,6972.13 U1.E22@8139.23,6991.48 ; U1.AC23@8099.86,7700.14 U1.AB22@8139.23,7660.77 ; v2(8120,7207.56) U1.K22@8139.23,7188.33 ; U1.G22@8139.23,7070.22 8139.23,7070.41 v2(8119.64,7090) U1.J21@8178.6,7148.96 ; U1.U22@8139.23,7463.92 U1.V21@8178.6,7503.29 ; U1.W22@8139.23,7542.66 v2(8120,7561.89) 8120,7562.8 U1.Y22@8139.23,7582.03 ; v2(8157.42,7364) U1.R21@8178.6,7385.18 ; U1.M21@8178.6,7267.07 v2(8198,7286.47) ; U1.E20@8217.97,6991.48 8237.49,7011 v2(8237.82,7011) U1.E19@8257.34,6991.48 ; U1.AB20@8217.97,7660.77 v2(8235.2,7678) 8240.11,7678 U1.AB19@8257.34,7660.77 ; U1.F18@8296.71,7030.85 8297.15,7030.85 v2(8317,7011) U1.E17@8336.08,6991.48 ; U1.AA18@8296.71,7621.4 U1.AB17@8336.08,7660.77 ; v2(8395,7641.22) U1.AA15@8414.82,7621.4 ; U1.F15@8414.82,7030.85 v2(8434,7011.67) ; U1.B14@8454.19,6873.37 v2(8472,6855.56) ; U1.AE13@8493.56,7778.88 v2(8514,7800) ; v2(8515,7012.92) U1.F12@8532.93,7030.85 ; U1.AA12@8532.93,7621.4 v2(8552,7640.47) ; U1.E10@8611.67,6991.48 U1.F9@8651.04,7030.85 ; U1.AB10@8611.67,7660.77 U1.AA9@8651.04,7621.4 ; U1.AB8@8690.41,7660.77 8710,7680.36 v2(8710,7680.55) U1.AB7@8729.78,7660.77 ; v2(8750,7286.22) U1.M6@8769.15,7267.07 ; U1.R6@8769.15,7385.18 v2(8788.33,7366) ; v2(8789,7483.44) U1.U5@8808.52,7463.92 ; v2(8789,7680.29) U1.AB5@8808.52,7660.77 ; U1.W5@8808.52,7542.66 8806.85,7542.66 v2(8788,7561.51) U1.Y5@8808.52,7582.03 ; v2(8828,6932.22) U1.D4@8847.89,6952.11 ; U1.C3@8887.26,6912.74 v2(8907,6893) ; U1.A2@8926.63,6834 U1.B1@8966,6873.37 U1.B2@8926.63,6873.37 ; U1.N2@8926.63,7306.44 v2(8947,7326) ; U1.AE2@8926.63,7778.88 8946,7798.25 v2(8946,7800) ; U1.AF2@8926.63,7818.25 U1.AE1@8966,7778.88
  TopLayer w10: v2(8593.19,6973) U1.E10@8611.67,6991.48 ; U1.E8@8690.41,6991.48 8692.82,6991.48 v2(8711.3,6973) U1.E7@8729.78,6991.48 ; U1.J6@8769.15,7148.96 v2(8788.91,7168.72) U1.K5@8808.52,7188.33 ; v2(8788,6972) U1.E5@8808.52,6991.48 ; U1.G5@8808.52,7070.22 8828,7089.7 v2(8828,7090.11) U1.H5@8808.52,7109.59
  TopLayer w12: v3(5080,6658) C19.2@5080,6613.46 5097.07,6630.53 U7.37@5170.72,6630.53 ; v3(5140,8854) 5151,8854 5182.77,8885.77 U2.112@5182.77,8922.31 ; v3(5160,7658) 5182.77,7635.23 U2.189@5182.77,7585.69 ; v3(5547,8858) 5576.47,8887.47 U2.92@5576.47,8922.31 ; v3(5560,7642) 5576.47,7625.53 U2.209@5576.47,7585.69 ; v1(5644.04,9238.04) U3.J1@5676,9238.04 ; v1(5655,9177.67) U3.K1@5676,9198.67 ; U3.B1@5676,9513.63 5606.37,9513.63 5582.99,9537.01 5582.99,9567.99 v3(5602,9587) 5642,9587 U3.A1@5676,9553 ; v1(5754.74,9169.74) U3.K3@5754.74,9198.67 ; U3.A3@5754.74,9553 v3(5754.74,9588.74) ; v1(5938,9618) 5938,9566.59 U3.A8@5951.59,9553 ; v1(5951.59,9176.41) U3.K8@5951.59,9198.67 ; U7.12@5966,6630.53 6076,6630.53 C27.1@6086.54,6620 v3(6086.54,6674.54) ; U2.231@6009.54,7585.69 6009.54,7630.54 v3(6040,7661) ; U2.70@6009.54,8922.31 6009.54,8867.46 v3(6040,8837) ; U3.K10@6030.33,9198.67 6079.67,9198.67 v3(6087,9206) 6054.96,9238.04 U3.J10@6030.33,9238.04 ; U3.B10@6030.33,9513.63 6070.64,9513.63 C7.2@6117.01,9560 ; U3.A10@6030.33,9553 C7.2@6110.01,9553 ; v3(6087.23,7830.77) U2.9@6274.31,7830.77 ; v3(6195.46,8657.54) U2.51@6274.31,8657.54 ; C20.2@6200,6793.46 6200,6809 v3(6225,6834) U8.43@6279.23,6834 ; U2.22@6274.31,8086.68 C104.1@6361,8088 6362,8089 v3(6362,8048) ; v1(6318.6,6777.6) U8.41@6318.6,6834 ; U8.49@6377.65,6364 v1(6377.65,6425.35) ; v1(6436.71,6763.29) U8.35@6436.71,6834 ; U8.55@6495.77,6364 v1(6495.77,6420.77) ; U8.29@6554.82,6834 6554.82,6779.18 6567,6767 v1(6717,6767) ; U8.15@6830.41,6834 6830.41,6886.41 6856,6912 6933,6912 v3(6948.52,6896.48) U8.9@6948.52,6834 ; U8.75@6889.47,6364 v1(6889.47,6409.47) ; U8.81@7007.57,6364 v1(7007.57,6415.57) ; U8.3@7066.63,6834 7066.63,6878.63 v1(7089,6901) 7106,6884 U8.1@7106,6834 ; U18.5@7300,7841.89 7341.89,7800 C133.2@7406.54,7800 7406.54,7900 R71.2@7400,7906.54 ; U19.39@7523.54,8353.94 v2(7610.94,8353.94) ; v2(7777.48,7923.48) U19.6@7777.48,8100 ; v2(7949.94,8353.94) U19.17@8031.42,8353.94 ; v3(8382,8554) U23.4@8463,8554 ; v3(8388,8599) U23.4@8458,8599 ; U20.1@8640,8540 v3(8640,8597) ; v3(8926,8850) FB3.1@8926.54,8895 ; v3(9173.47,6590) R61.2@9173.46,6640 ; U22.8@9442.36,7875 9558.46,7875 C162.2@9560,7873.46 v2(9560,7928)
  TopLayer w16: C150.1@7840,6755.12 7840,6798 7915.37,6873.37 U1.B26@7981.75,6873.37 ; C147.1@7840,7744.88 7884.88,7744.88 v2(7918.88,7778.88) U1.AE26@7981.75,7778.88 ; U1.B1@8966,6873.37 8979.37,6860 9026.26,6860 v3(9039.63,6873.37)
  TopLayer w20: C7.2@6117.01,9560 v3(6117.01,9591.99) ; U6.4@6540,9096 6566.54,9069.46 6566.54,8881.46 v3(6585,8863) ; U4.4@6964,8220 6977.46,8206.54 v3(7189.54,8206.54)
  TopLayer w40: C135.1@6880,9417 C135.1@6880.05,9417
  BottomLayer w6: v1(8846.54,8159.54) R74.2@8846.54,8200 ; R80.2@8913.46,8100 v1(8913.46,8141.46)
  BottomLayer w8: R57.1@4835,6164.54 R56.1@4961.54,6164.54 ; R88.1@7611,8215.54 v1(7611,8241) ; R87.1@7733.46,8300 v1(7779,8300) ; C49.1@8000,7780 8020,7780 v2(8040,7760) ; C75.1@8040,6860 8040.55,6860.55 v2(8040.55,6892.81) ; C65.1@8099.86,7660.77 8118.71,7679.63 v2(8120.37,7679.63) 8120.37,7719.63 C58.1@8120,7720 ; C74.1@8100,6962 8110,6972 v2(8120,6972) ; C57.1@8100,7600 8120,7580 v2(8120,7561.89) ; v2(8119.64,7090) 8150,7090 C69.1@8160,7100 ; v2(8120,7207.56) 8132.44,7220 C68.1@8160,7220 ; C67.1@8140,7380 8156,7364 v2(8157.42,7364) ; v2(8158.69,7483.39) 8158.69,7518.69 C66.1@8160,7520 ; C40.1@8180,7720 8222,7678 8238,7678 C56.1@8240,7720 ; v2(8237.82,7011) 8240,7008.82 C73.1@8240,6980 ; v2(8317,7011) 8317,7003 C76.1@8340,6980 ; v2(8395,7641.22) 8401.22,7641.22 C48.1@8420,7660 ; v2(8434,7011.67) 8434,6988 C83.1@8440,6982 ; C37.1@8480,7740 8473,7747 8493,7773 v2(8514,7800) ; v2(8515,7012.92) 8515,6987 C77.1@8520,6982 ; C46.1@8540,7680 8552,7668 v2(8552,7640.47) ; C39.1@8620,7698 8630,7688 v2(8630,7643) ; C86.1@8680,6940 8680,6941.7 v2(8711.3,6973) ; C38.1@8680,7698 8692.55,7698 v2(8710,7680.55) ; v2(8750,7286.22) 8776.77,7286.22 R78.2@8780,7282.99 ; v2(8789,7680.29) 8806.71,7698 C41.1@8820,7698 ; C45.1@8900,7820 8920,7800 v2(8946,7800)
  BottomLayer w10: C85.1@8760,6980 8770,6970 v2(8788,6972) ; C84.1@8780,7140 8780,7159.81 v2(8788.91,7168.72)
  BottomLayer w12: R29.2@5133.46,8340 5178,8340 v3(5193,8325) ; C110.1@5140,8820 v3(5140,8854) ; v3(5160,7658) C98.1@5160,7700 ; v3(5547,8858) 5547,8833 C114.1@5560,8820 ; v3(5560,7642) C109.1@5560,7700 ; C10.2@5620,9202.99 5620,9214 v1(5644.04,9238.04) ; v1(5655,9177.67) 5655,9167.99 C6.2@5680,9142.99 ; R8.2@5700,9713.46 v3(5700,9761) ; C5.2@5740,9142.99 5754.74,9157.73 v1(5754.74,9169.74) ; v3(5754.74,9588.74) 5780,9614 C11.2@5780,9639.01 ; v1(5938,9618) 5940,9620 C8.2@5977.01,9620 ; v1(5951.59,9176.41) 5973.42,9176.41 C16.2@5980,9182.99 ; v3(6040,7661) C105.1@6040,7700 ; C99.1@6040,8820 v3(6040,8837) ; C119.1@6058,7838 6080,7838 v3(6087.23,7830.77) ; C115.1@6140,8660 6193,8660 v3(6195.46,8657.54) ; C24.2@6353.46,6460 6377.65,6435.81 v1(6377.65,6425.35) ; v1(6436.71,6763.29) 6436.71,6696.75 C21.2@6440,6693.46 ; v1(6495.77,6420.77) 6495.77,6442.3 C25.2@6513.46,6460 ; v3(6741,8096) 6755,8082 U5.3@6755,8017.64 ; U5.7@6805,8222.36 6805,8273 6817,8285 v3(6833,8285) 6855,8263 U5.8@6855,8222.36 ; v1(6889.47,6409.47) C26.2@6943,6458 ; v1(7089,6901) 7108,6920 C22.2@7126.54,6920 ; v2(7610.94,8353.94) 7657,8400 C158.2@7666.54,8400 ; R88.1@7611,8215.54 R88.1@7626.54,8200 ; C154.2@7880,8346.54 7887.4,8353.94 v2(7949.94,8353.94) ; C165.2@8340,8533.46 8360.54,8554 v3(8382,8554)
  BottomLayer w16: v2(8946,7800) 8990.88,7844.88 C144.1@9020,7844.88 ; v3(9039.63,6873.37) 9064.06,6873.37 C152.1@9100,6837.43
  BottomLayer w20: C14.1@5537.43,9580 5544.43,9587 v3(5602,9587) ; v3(6087,9206) 6121.03,9171.97 C15.1@6121.03,9121.29 ; v3(7401,8226) FB4.2@7402,8278.54
  other v2: 4898,6164.54 7900,6858 8631,7012 8316.21,7640.91
  other v3: 7406.54,7855 6888,8073.46 6796,9420 6827,9421 4951,9500
V3.3A: C153.2 C155.2 C157.2 C159.2 FB4.1 U19.25 U19.28 U19.31 U19.36 | length 915.9
  TopLayer w12: v2(7445.89,8448.43) U19.36@7523.54,8448.43 ; v2(7682.99,8526.54) U19.31@7682.99,8607.87 ; v2(7777.48,8528.05) U19.28@7777.48,8607.87 ; v2(7871.97,8528.97) U19.25@7871.97,8607.87
  BottomLayer w20: FB4.1@7400,8353.46 C159.2@7400,8446.54 7540,8446.54 C157.2@7620,8526.54 C155.2@7740,8526.54 v2(7871.97,8528.97)
V5: C96.2 C127.2 C134.1 C136.1 C139.1 C140.1 C146.1 C166.2 J2.A1 J2.A25 J2.B2 J2.B24 J2.D3 J2.D23 J2.E1 J2.E25 J3.1 JP6.12 R62.2 R64.1 R66.2 R73.2 U9.15 U10.15 U11.15 U14.2 U15.14 U15.15 U15.16 U16.1 U17.1 | length 1756.3
  TopLayer w8: C166.2@9420,7593.46 9420,7615 v2(9429.41,7624.41) ; v2(9429.41,7195.59) U11.15@9500,7195.59
  TopLayer w12: R64.1@8153.46,9600 v3(8215,9600) ; R73.2@8153.46,9700 v3(8214,9700) ; v3(8214.46,9386.54) R66.2@8260,9386.54 ; C134.1@8586,9751 v3(8649,9751) ; C134.1@8587,9675 v3@8645,9675 ; C134.1@8588,9719 v3(8648,9719) ; R62.2@9113.46,9020 9190,9020 v3(9219,9049)
  TopLayer w40: 7039,9553 v3@7320,9553 ; v3@7060,9048 v3(7062.12,9045.88) C136.1@7159,9045.88 7182.88,9022 U16.1@7429,9022 ; C96.2@7279,9047.54 7304.54,9022
  BottomLayer w8: v2(9429.41,7624.41) U9.15@9500,7624.41 ; v2(9431.59,7124.41) U10.15@9500,7124.41
  BottomLayer w20: C139.1@4933.46,9018.35 C139.1@4961,9045.88
  BottomLayer w40: v3(4933.46,8876.54) C127.2@4933.46,8920 4961,8947.54 U17.1@4961,9175
  other v3: 7091,9045.88 9261,9049 9262,9083 9221,9084 7052,9553 7309,9553 8649,9685
VCCA_PLL1: C128.2 C130.2 C141.1 FB1.2 U2.27 | length 459.1
  TopLayer w8: v3(6175,8185) U2.27@6274.31,8185.1
  BottomLayer w8: FB1.2@5820,8173.46 C130.2@6120,8173.46 6131.54,8185 v3(6175,8185)
VCCA_PLL2: C129.2 C131.2 C142.1 FB2.2 U2.154 | length 428.9
  TopLayer w12: U2.154@4937.69,8185.1 v3(5008.1,8185.1)
  BottomLayer w8: C131.2@5064.64,8185.1 C131.2@5066,8186.46
  BottomLayer w12: v3(5008.1,8185.1) C131.2@5064.64,8185.1 ; C131.2@5066,8186.46 FB2.2@5366,8186.46
VP0_27MHZ: R76.2 U1.AF14 | length 230.7
  TopLayer w8: U1.AF14@8454.19,7818.25 8454.19,8040.72 R76.2@8460,8046.54
VP0_CLK1: U1.AF12 U19.4 | length 1040.9
  TopLayer w6: U19.4@7714.49,8100 7714.49,8156 7732.49,8174 7951,8174 8075,8050 v1(8298,8050) ; U1.AF12@8532.93,7818.25 v1(8532.93,7838.07)
  BottomLayer w6: v1(8298,8050) 8321,8050 v1(8532.93,7838.07)
VP0_HSYNC: U1.AE17 U19.8 | length 735.5
  TopLayer w6: U19.8@7840.47,8100 7840.47,8030.53 7923,7948 8280,7948 8316,7912 8316,7798.96 U1.AE17@8336.08,7778.88
VP0_VSYNC: U1.AC17 U19.7 | length 823.2
  TopLayer w6: U19.7@7808.98,8100 7808.98,8024.02 7915,7918 v1(8265,7918) ; v1(8315,7721.22) U1.AC17@8336.08,7700.14
  BottomLayer w6: v1(8265,7918) 8315,7868 v1(8315,7721.22)
VP0D2: U1.AF17 U19.16 | length 680.3
  TopLayer w6: U19.16@8031.42,8322.44 v1(8116.56,8322.44) ; v1(8171,8230) 8336.08,8064.92 U1.AF17@8336.08,7818.25
  BottomLayer w6: v1(8116.56,8322.44) 8171,8268 v1(8171,8230)
VP0D3: U1.AF16 U19.15 | length 700.8
  TopLayer w6: U19.15@8031.42,8290.94 8177.5,8290.94 8375.45,8093 U1.AF16@8375.45,7818.25
VP0D4: U1.AE16 U19.14 | length 708.7
  TopLayer w6: U19.14@8031.42,8259.45 8031.87,8259 8178,8259 8356,8081 8356,7798.33 U1.AE16@8375.45,7778.88
VP0D5: U1.AD16 U19.13 | length 693.4
  TopLayer w6: U19.13@8031.42,8227.95 8138.05,8227.95 v1(8262,8104) ; v1(8356,7758.96) U1.AD16@8375.45,7739.51
  BottomLayer w6: v1(8262,8104) 8262,7976 8356,7882 v1(8356,7758.96)
VP0D6: U1.AC16 U19.12 | length 695.1
  TopLayer w6: U19.12@8031.42,8196.46 8127.54,8196.46 v1(8234.79,8089.21) ; v1(8356,7719.59) U1.AC16@8375.45,7700.14
  BottomLayer w6: v1(8234.79,8089.21) 8234.79,7978.21 8335,7878 8335,7740.59 v1(8356,7719.59)
VP0D7: U1.AB16 U19.11 | length 754.2
  TopLayer w6: U19.11@7934.96,8100 7934.96,8032.04 7947,8020 v1(8129,8020) ; v1(8356.22,7680) U1.AB16@8375.45,7660.77
  BottomLayer w6: v1(8129,8020) 8297,7852 8297,7695 8312,7680 v1(8356.22,7680)
VP0D8: U1.AE15 U19.10 | length 753.8
  TopLayer w6: U19.10@7903.47,8100 7903.47,8030.53 7936,7998 v1(8313.08,7998) ; v1(8394,7799.7) U1.AE15@8414.82,7778.88
  BottomLayer w6: v1(8313.08,7998) 8394,7917.08 v1(8394,7799.7)
VP0D9: U1.AD15 U19.9 | length 799.7
  TopLayer w6: U19.9@7871.97,8100 7871.97,8030.03 7923,7979 v1(8289,7979) ; v1(8394,7760.33) U1.AD15@8414.82,7739.51
  BottomLayer w6: v1(8289,7979) 8373,7895 8373,7781.33 v1(8394,7760.33)
XSPCLK: U1.R5 U22.2 | length 743.3
  TopLayer w6: v1(8788,7405.7) U1.R5@8808.52,7385.18 ; v1(9038,7723) 9140,7825 U22.2@9237.64,7825
  BottomLayer w6: v1(8788,7405.7) 8788,7447 8815,7474 8815,7588 8858,7631 8946,7631 v1(9038,7723)
XSPCS: U1.T4 U22.1 | length 784.3
  TopLayer w6: v1(8829,7443.44) U1.T4@8847.89,7424.55 ; v1(9088,7860) 9103,7875 U22.1@9237.64,7875
  BottomLayer w6: v1(8829,7443.44) 8848,7462.44 8848,7583 8867,7602 8959,7602 9034,7677 9075,7677 9088,7690 v1(9088,7860)
XSPDI: U1.R4 U22.4 | length 690.8
  TopLayer w6: v1(8829,7404.07) U1.R4@8847.89,7385.18 ; v1(9060,7698) 9087,7725 U22.4@9237.64,7725
  BottomLayer w6: v1(8829,7404.07) 8809,7424.07 8809,7451.03 8834.82,7476.85 8834.82,7590.82 8862,7618 8955,7618 9035,7698 v1(9060,7698)
XSPDO: U1.P5 U22.3 | length 2289.4
  TopLayer w6: v1(8789,7326.29) U1.P5@8808.52,7345.81 ; v1(8870,6711) 8889,6730 v1(9238,6730) ; U22.3@9237.64,7775 v1(9363,7775)
  BottomLayer w6: v1(8789,7326.29) 8826,7289.29 8826,7138 8808,7120 8808,6773 v1(8870,6711) ; v1(9238,6730) 9349,6841 9349,7724 9363,7738 v1(9363,7775)
pads on no net: J1.6 J2.A15 J2.A17 J2.A19 J2.A21 J2.A23 J2.C8 J2.C10 J2.C16 J2.C18 J2.C20 J2.C22 J2.C24 J2.D25 J5.A1 J5.A2 J5.A3 J5.A4 J5.A5 J5.A6 J5.A7 J5.A8 J5.A9 J5.A10 J5.A11 J5.A12 J5.A13 J5.A14 J5.A15 J5.A19 J5.A20 J5.A21 J5.A22 J5.B2 J5.B4 J5.B5 J5.B6 J5.B8 J5.B10 J5.B12 J5.B14 J5.B19 J5.B20 J5.B21 J5.B22 J5.C1 J5.C2 J5.C3 J5.C4 J5.C5 J5.C6 J5.C7 J5.C8 J5.C9 J5.C10 J5.C11 J5.C12 J5.C13 J5.C14 J5.C15 J5.C16 J5.C17 J5.C19 J5.C20 J5.C21 J5.C22 J5.D1 J5.D2 J5.D3 J5.D5 J5.D7 J5.D9 J5.D11 J5.D13 J5.D15 J5.D19 J5.D21 J5.D22 J5.E1 J5.E2 J5.E3 J5.E4 J5.E5 J5.E6 J5.E7 J5.E8 J5.E9 J5.E10 J5.E11 J5.E12 J5.E13 J5.E14 J5.E15 J5.E19 J5.E20 J5.E21 J5.E22 JP3.3 JP3.5 JP4.6 JP4.7 JP4.8 S2.3 S2.4 U1.A4 U1.A5 U1.A7 U1.A9 U1.A10 U1.A11 U1.A13 U1.A17 U1.AA2 U1.AA3 U1.AA23 U1.AA24 U1.AA25 U1.AA26 U1.AB3 U1.AB11 U1.AB12 U1.AB13 U1.AB14 U1.AB15 U1.AB23 U1.AB24 U1.AB25 U1.AC1 U1.AC4 U1.AC6 U1.AC7 U1.AC8 U1.AC9 U1.AC10 U1.AC11 U1.AC12 U1.AC13 U1.AC14 U1.AC15 U1.AC19 U1.AC20 U1.AC21 U1.AC25 U1.AC26 U1.AD3 U1.AD5 U1.AD6 U1.AD7 U1.AD8 U1.AD9 U1.AD10 U1.AD11 U1.AD12 U1.AD13 U1.AD14 U1.AD17 U1.AD19 U1.AD20 U1.AD21 U1.AD22 U1.AD23 U1.AD25 U1.AD26 U1.AE5 U1.AE6 U1.AE7 U1.AE9 U1.AE11 U1.AE18 U1.AE20 U1.AE21 U1.AE22 U1.AE23 U1.AF3 U1.AF4 U1.AF5 U1.AF6 U1.AF8 U1.AF10 U1.AF18 U1.AF20 U1.AF21 U1.AF23 U1.AF24 U1.B8 U1.B9 U1.B10 U1.B11 U1.B12 U1.B15 U1.B16 U1.B17 U1.C7 U1.C8 U1.C9 U1.C10 U1.C11 U1.C12 U1.C15 U1.C16 U1.C17 U1.D6 U1.D7 U1.D8 U1.D9 U1.D10 U1.D11 U1.D12 U1.D15 U1.D16 U1.D17 U1.E11 U1.E12 U1.E13 U1.E14 U1.L22 U1.M5 U1.M22 U1.N22 U1.P22 U1.R22 U1.R25 U1.R26 U1.T22 U1.T23 U1.W7 U1.W23 U1.W24 U1.Y23 U1.Y24 U1.Y25 U1.Y26 U2.18 U2.19 U2.20 U2.21 U2.23 U2.38 U2.123 U2.124 U2.125 U2.126 U2.127 U2.128 U2.131 U2.132 U2.133 U2.134 U2.135 U2.136 U2.137 U2.138 U2.139 U2.140 U2.141 U2.156 U2.158 U2.159 U2.160 U2.161 U2.162 U2.163 U2.166 U2.167 U2.168 U2.169 U3.B8 U3.F9 U3.H10 U3.J9 U4.1 U6.1 U7.9 U7.10 U7.13 U7.14 U7.15 U7.30 U7.32 U7.34 U7.36 U7.39 U7.41 U7.43 U8.14 U8.30 U8.57 U8.69 U8.70 U8.73 U9.1 U9.36 U9.37 U9.38 U9.39 U9.40 U9.42 U9.43 U9.44 U9.45 U9.46 U10.1 U11.1 U14.5 U19.1 U19.20 U19.22 U19.23 U19.24 U19.26 U19.27 U19.29 U19.34 U19.37 U19.43 U21.1 U22.6 U22.7 U23.1
copper on no net:
  other v4: 4121.02,7758.19 4121.02,8029.84

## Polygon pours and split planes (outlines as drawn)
GND on GROUND (split plane): 4026.01,6324.02 4243.02,6324.02 4243.02,6032.02 10266.99,6032.02 10266.99,9906.99 4245.02,9906.99 4245.02,9609.99 4026.01,9609.99 4026.01,8154.02 4564,8154.02 cw(c4564,8139) 4574.63,8149.6 4574.62,8149.62 4676.22,8048.02 5525.78,8048.02 5624.98,8147.22 5624.98,8358 cw(c5640,8358) 5629.4,8368.63 5629.38,8368.62 5945.38,8684.62 5945.37,8684.6 cw(c5956,8674) 5956,8689.01 6110.98,8689.01 6110.98,8782 cw(c6126,8782) 6115.32,8792.56 6204.32,8882.56 cw(c6215,8872) 6214.93,8887.01 6357.86,8888.01 cw(c6358,8873) 6358,8888.01 7905,8888.01 cw(c7905,8873) 7920.02,8873 7920.02,8603 cw(c7905,8603) 7905,8587.99 7587.22,8587.99 7493.62,8494.38 7493.63,8494.4 cw(c7483,8505) 7483,8489.99 7273,8489.99 cw(c7273,8505) 7257.98,8505 7257.98,8559.99 7068.22,8559.99 6985.62,8477.38 6985.63,8477.4 cw(c6975,8488) 6975,8472.99 5963.22,8472.99 5815.02,8324.78 5815.02,8048 cw(c5800,8048) 5810.6,8037.37 5810.62,8037.38 5678.62,7905.38 5678.63,7905.4 cw(c5668,7916) 5668,7900.98 4711.22,7900.98 4513.62,7703.38 4513.63,7703.4 cw(c4503,7714) 4503,7698.98 4026.01,7698.98
AGND on GROUND (split plane): 4026.01,7729.02 4496.78,7729.02 4694.38,7926.62 4694.37,7926.6 cw(c4705,7916) 4705,7931.02 5661.78,7931.02 5784.98,8054.22 5784.98,8331 cw(c5800,8331) 5789.4,8341.63 5789.38,8341.62 5946.38,8498.62 5946.37,8498.6 cw(c5957,8488) 5957,8503.01 6968.78,8503.01 7051.38,8585.62 7051.37,8585.6 cw(c7062,8575) 7062,8590.01 7273,8590.01 cw(c7273,8575) 7288.02,8575 7288.02,8520.01 7476.78,8520.01 7570.38,8613.62 7570.37,8613.6 cw(c7581,8603) 7581,8618.01 7889.98,8618.01 7889.98,8857.99 7446.02,8857.99 7446.02,8697 cw(c7436,8697) 7443.08,8689.92 7417.08,8663.92 cw(c7410,8671) 7410,8660.99 7310,8660.99 cw(c7310,8671) 7299.98,8671 7299.98,8799.99 6229.15,8799.99 6197.02,8767.85 6197.02,8622 cw(c6187,8622) 6187,8611.99 5983.15,8611.99 5703.02,8331.85 5703.02,8108 cw(c5693,8108) 5700.08,8100.92 5572.08,7972.92 cw(c5565,7980) 5565,7969.98 4643.15,7969.98 4477.08,7803.92 cw(c4470,7811) 4470,7800.98 4311,7800.98 cw(c4311,7811) 4302.98,7817.01 4302.98,8123.98 4026.01,8123.98
CVBS on GROUND (split plane): 4323.02,7821.02 4465.85,7821.02 4631.92,7987.08 cw(c4639,7980) 4639,7990.02 5560.85,7990.02 5682.98,8112.15 5682.98,8336 cw(c5693,8336) 5685.92,8343.08 5971.92,8629.08 cw(c5979,8622) 5979,8632.01 6176.98,8632.01 6176.98,8772 cw(c6187,8772) 6179.92,8779.08 6217.92,8817.08 cw(c6225,8810) 6225,8820.01 7310,8820.01 cw(c7310,8810) 7320.02,8810 7320.02,8681.01 7405.85,8681.01 7425.98,8701.15 7425.98,8857.99 6358.05,8857.99 6358.1,8857.99 6358.05,8857.99 6221.31,8857.03 6141.02,8775.83 6141.02,8674 cw(c6126,8674) 6126,8658.99 5962.22,8658.99 5655.02,8351.78 5655.02,8141 cw(c5640,8141) 5650.6,8130.37 5650.62,8130.38 5542.62,8022.38 5542.63,8022.4 cw(c5532,8033) 5532,8017.98 4670,8017.98 cw(c4670,8033) 4659.37,8022.4 4659.38,8022.38 4557.78,8123.98 4323.02,8123.98
V5 on VCC (split plane): 4883.02,8829.01 5005.98,8829.01 5005.98,8869 cw(c5021,8869) 5010.4,8879.63 5010.38,8879.62 5113.38,8982.62 5113.37,8982.6 cw(c5124,8972) 5124,8987.01 9236,8987.01 cw(c9236,8972) 9251.01,8972 9251.01,8126.02 9695,8126.02 cw(c9695,8111) 9710.01,8111 9710.01,7694 cw(c9695,7694) 9695,7678.98 9358.01,7678.98 9358.01,6682.02 9695,6682.02 cw(c9695,6667) 9710.01,6667 9710.01,6085.02 10217.99,6085.02 10217.99,9855.99 6729.02,9855.99 6729.02,9501.89 7328.73,9497.06 cw(c7334,9483) 7349.02,9483 7349.02,9244 cw(c7334,9244) 7334,9228.99 6942.02,9228.99 6942.02,9133 cw(c6927,9133) 6927,9117.99 4883.02,9117.99
V1.4 on VCC (split plane): 8170.02,7030.15 8184.15,7016.02 8190.85,7016.02 8234.92,7060.08 cw(c8242,7053) 8242,7063.02 8668,7063.02 cw(c8668,7053) 8675.08,7060.08 8714.15,7021.02 8777.85,7021.02 8794.99,7038.15 8794.99,7054.85 8727.92,7121.92 cw(c8735,7129) 8724.99,7129 8724.99,7154 cw(c8735,7154) 8727.92,7161.08 8772.99,7206.15 8772.99,7218.85 8750.85,7240.98 8725,7240.98 cw(c8725,7251) 8714.99,7251 8714.99,7356 cw(c8725,7356) 8717.92,7363.08 8761.99,7407.15 8761.99,7467.85 8745.92,7483.92 cw(c8753,7491) 8742.99,7491 8742.99,7563 cw(c8753,7563) 8745.92,7570.08 8778.99,7603.15 8778.99,7630.98 8687.01,7630.98 8687.01,7602 cw(c8677,7602) 8677,7591.98 8526,7591.98 cw(c8526,7602) 8515.99,7602 8515.99,7735.85 8249.92,8001.92 cw(c8257,8009) 8246.99,8009 8246.99,8956.99 7813.02,8956.99 7813.02,8594.01 8002,8594.01 cw(c8002,8584) 8012.02,8584 8012.02,7962.15 8268.15,7706.02 8393,7706.02 cw(c8393,7696) 8400.08,7703.08 8439.08,7664.08 cw(c8432,7657) 8442.01,7657 8442.01,7605 cw(c8432,7605) 8432,7594.98 8255,7594.98 cw(c8255,7605) 8247.92,7597.92 8211.85,7633.98 8164.02,7633.98 8164.02,7540.15 8199.08,7505.08 cw(c8192,7498) 8202.01,7498 8202.01,7476 cw(c8192,7476) 8199.08,7468.92 8174.02,7443.85 8174.02,7413.15 8205.08,7382.08 cw(c8198,7375) 8208.01,7375 8208.01,7327.15 8235.08,7300.08 cw(c8228,7293) 8238.01,7293 8238.01,7277 cw(c8228,7277) 8235.08,7269.92 8170.02,7204.85
V1.5 on VCC (split plane): 5206.02,7706.02 6002.98,7706.02 6002.98,7835 cw(c6018,7835) 6007.4,7845.63 6007.38,7845.62 6524.38,8362.62 6524.37,8362.6 cw(c6535,8352) 6535,8367.01 7388.78,8367.01 7616.38,8594.62 7616.37,8594.6 cw(c7627,8584) 7627,8599.01 7782.98,8599.01 7782.98,8956.99 6807.22,8956.99 6433.62,8583.38 6433.63,8583.4 cw(c6423,8594) 6423,8578.99 6130,8578.99 cw(c6130,8594) 6114.98,8594 6114.98,8798.99 5177.02,8798.99 5177.02,8443.22 5281.62,8338.62 5281.6,8338.63 cw(c5271,8328) 5286.02,8328 5286.02,7971 cw(c5271,7971) 5281.6,7960.37 5281.62,7960.38 5206.02,7884.78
